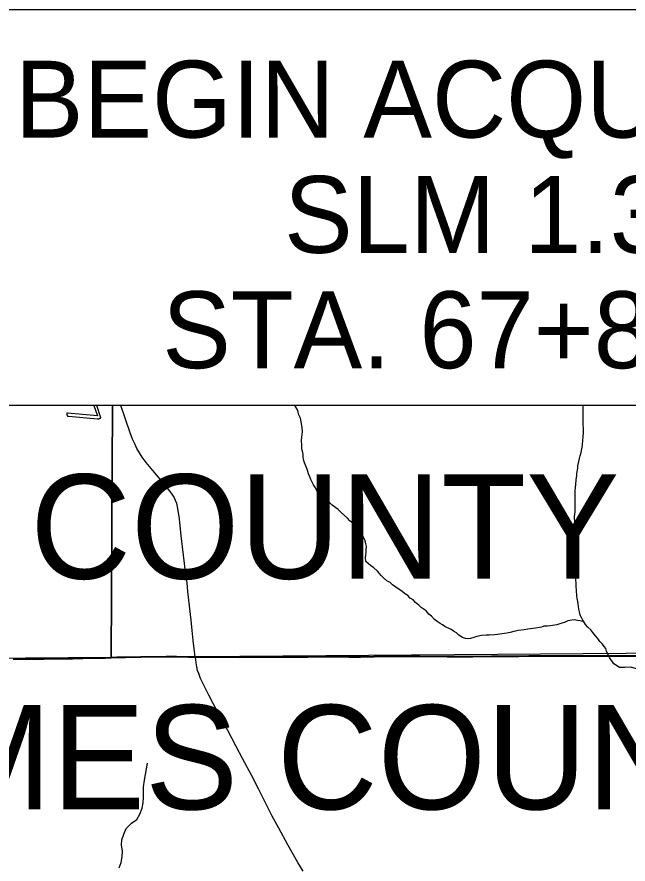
# Model space of a CAD drawing. Extents: x 0 to 34, y 0 to 22.
# Drawn here: x 4.059 to 5.172, y 15.823 to 17.365 of the extents above; entities that cross this region are included whole.
import ezdxf

# ---------------------------------------------------------------- set-up
doc = ezdxf.new("R2010")
doc.units = 0
for name, color, linetype in [('Default', 7, 'Continuous'), ('GM_X_County_Road', 7, 'Continuous'), ('GM_X_County_Road_Text', 7, 'Continuous'), ('GM_X_Minor_River', 7, 'Continuous'), ('GM_X_Section', 7, 'Continuous'), ('GM_X_Township_Road', 7, 'Continuous'), ('SH_Cut_Line', 7, 'Continuous')]:
    doc.layers.add(name, color=color, linetype=linetype)

msp = doc.modelspace()

# ---------------------------------------------------------------- linework, layer by layer
at = {"layer": 'Default'}
msp.add_lwpolyline([(3.9922, 17.3788), (5.9096, 17.3788), (5.9096, 16.6576), (3.9922, 16.6576)], close=True, dxfattribs=at)
for points in [[(4.0522, 16.1955), (4.0893, 16.196), (4.1079, 16.1964), (4.1358, 16.1969), (4.1606, 16.1968), (4.1792, 16.1971), (4.2195, 16.1983), (4.2412, 16.1991), (4.2567, 16.1994), (4.2846, 16.1997), (4.3311, 16.2004), (4.3498, 16.2004), (4.3715, 16.2), (4.3836, 16.2), (4.3963, 16.1999), (4.4243, 16.1997), (4.4646, 16.1994), (4.5174, 16.1997), (4.5887, 16.2), (4.6228, 16.2003), (4.6414, 16.2003), (4.663, 16.2), (4.6846, 16.2001), (4.7092, 16.2006), (4.7309, 16.201), (4.7433, 16.2011), (4.7587, 16.201), (4.7928, 16.2009), (4.8425, 16.2006), (4.8735, 16.2004), (4.889, 16.2007), (4.9231, 16.2011), (4.9448, 16.2013), (4.9727, 16.2014), (4.9914, 16.2016), (5.0069, 16.2018), (5.0348, 16.2017), (5.0689, 16.2016), (5.1, 16.2016), (5.1341, 16.2015), (5.1683, 16.2016), (5.2087, 16.2016)], [(5.2087, 16.2016), (5.1683, 16.2016), (5.1341, 16.2015), (5.1, 16.2016), (5.0689, 16.2016), (5.0348, 16.2017), (5.0069, 16.2018), (4.9914, 16.2016), (4.9727, 16.2014), (4.9448, 16.2013), (4.9231, 16.2011), (4.889, 16.2007), (4.8735, 16.2004), (4.8425, 16.2006), (4.7928, 16.2009), (4.7587, 16.201), (4.7433, 16.2011), (4.7309, 16.201), (4.7092, 16.2006), (4.6846, 16.2001), (4.663, 16.2), (4.6414, 16.2003), (4.6228, 16.2003), (4.5887, 16.2), (4.5174, 16.1997), (4.4646, 16.1994), (4.4243, 16.1997), (4.3963, 16.1999), (4.3836, 16.2), (4.3715, 16.2), (4.3498, 16.2004), (4.3311, 16.2004), (4.2846, 16.1997), (4.2567, 16.1994), (4.2412, 16.1991), (4.2195, 16.1983), (4.1792, 16.1971), (4.1606, 16.1968), (4.1358, 16.1969), (4.1079, 16.1964), (4.0893, 16.196), (4.0522, 16.1955)]]:
    msp.add_lwpolyline(points, dxfattribs=at)
at = {"layer": 'GM_X_County_Road'}
for points in [[(4.3838, 16.1994), (4.3832, 16.2047), (4.3802, 16.2294), (4.3781, 16.248), (4.3762, 16.2665), (4.3705, 16.3189), (4.3688, 16.3344), (4.3669, 16.3498), (4.3583, 16.4204), (4.3549, 16.4513), (4.3529, 16.4667), (4.3516, 16.4729), (4.35, 16.4789), (4.3479, 16.4849), (4.3452, 16.4906), (4.342, 16.496), (4.3384, 16.5011), (4.3267, 16.5157), (4.3065, 16.5395), (4.2947, 16.5538), (4.2871, 16.5636), (4.2821, 16.5714), (4.2776, 16.5795), (4.2735, 16.5878), (4.2698, 16.5963), (4.2654, 16.6079), (4.2564, 16.6344), (4.2483, 16.6576)], [(4.5801, 15.8093), (4.5707, 15.8254), (4.5523, 15.8578), (4.5358, 15.8878), (4.5241, 15.9098), (4.51, 15.9375), (4.4988, 15.9596), (4.4859, 15.9845), (4.47, 16.0148), (4.4585, 16.0368), (4.4422, 16.0668), (4.4245, 16.0996), (4.4087, 16.1299), (4.3973, 16.1521), (4.3934, 16.1606), (4.39, 16.1694), (4.3881, 16.1753), (4.3868, 16.1815), (4.3855, 16.1891), (4.3846, 16.1953), (4.3842, 16.1978), (4.3838, 16.1994)]]:
    msp.add_lwpolyline(points, dxfattribs=at)
at = {"layer": 'GM_X_County_Road_Text'}
msp.add_line((4.1528, 16.638), (4.2061, 16.6336), dxfattribs=at)
msp.add_lwpolyline([(4.2115, 16.6368), (4.2044, 16.6576), (4.1994, 16.6576), (4.2058, 16.6386), (4.1513, 16.6435)], dxfattribs=at)
for points in [[(4.1498, 16.6431), (4.1497, 16.6429), (4.1497, 16.6423)], [(4.1497, 16.6423), (4.1498, 16.6417), (4.1501, 16.6408)], [(4.1504, 16.6435), (4.15, 16.6434), (4.1498, 16.6431)], [(4.1501, 16.6408), (4.1504, 16.64), (4.1506, 16.6395)], [(4.1513, 16.6435), (4.1507, 16.6435), (4.1504, 16.6435)], [(4.1506, 16.6395), (4.1509, 16.639), (4.1511, 16.6386)], [(4.1511, 16.6386), (4.1514, 16.6383), (4.1518, 16.6382)], [(4.1518, 16.6382), (4.1522, 16.638), (4.1528, 16.638)], [(4.2061, 16.6336), (4.2066, 16.6336), (4.2071, 16.6336)], [(4.2071, 16.6336), (4.2076, 16.6336), (4.2081, 16.6337)], [(4.2081, 16.6337), (4.2085, 16.6337), (4.209, 16.6339)], [(4.209, 16.6339), (4.2094, 16.634), (4.2099, 16.6341)], [(4.2099, 16.6341), (4.2105, 16.6343), (4.2109, 16.6346)], [(4.2109, 16.6346), (4.2112, 16.6348), (4.2115, 16.6351)], [(4.2117, 16.6358), (4.2117, 16.6363), (4.2115, 16.6368)], [(4.2115, 16.6351), (4.2117, 16.6354), (4.2117, 16.6358)]]:
    msp.add_open_spline(points, degree=2, dxfattribs=at)
at = {"layer": 'GM_X_Minor_River'}
for points in [[(4.5775, 16.5946), (4.5778, 16.6), (4.5788, 16.6098), (4.5787, 16.6174), (4.5767, 16.628), (4.5755, 16.6348), (4.5724, 16.6409), (4.5709, 16.6454), (4.5701, 16.6496), (4.5662, 16.656), (4.5653, 16.6576)], [(5.1379, 16.1989), (5.1327, 16.21), (5.1312, 16.2149), (5.1281, 16.219), (5.1254, 16.2232), (5.1204, 16.2281), (5.1166, 16.2333), (5.1127, 16.2379), (5.1074, 16.2443), (5.1043, 16.2492), (5.0986, 16.254), (5.0943, 16.2589), (5.0897, 16.2665), (5.0878, 16.2706), (5.0847, 16.2759), (5.0835, 16.282), (5.0823, 16.2865), (5.0815, 16.2918), (5.0807, 16.2964), (5.0803, 16.3005), (5.0791, 16.3059), (5.0783, 16.3112), (5.0778, 16.321), (5.0773, 16.3278), (5.0773, 16.3328), (5.0768, 16.3411), (5.0767, 16.3529), (5.0763, 16.3608), (5.0762, 16.3662), (5.0757, 16.379), (5.0753, 16.3832), (5.0748, 16.3889), (5.0747, 16.4056), (5.0742, 16.4174), (5.074, 16.4329), (5.0747, 16.4435), (5.0745, 16.4553), (5.0756, 16.464), (5.0755, 16.4701), (5.0758, 16.48), (5.0754, 16.4868), (5.0753, 16.4963), (5.0756, 16.5016), (5.0763, 16.5088), (5.0766, 16.513), (5.0773, 16.5229), (5.0783, 16.5293), (5.0787, 16.5339), (5.0801, 16.5434), (5.0804, 16.5479), (5.0822, 16.5555), (5.0833, 16.5612), (5.0848, 16.5658), (5.0862, 16.5723), (5.0884, 16.5818), (5.0891, 16.5867), (5.0901, 16.6015), (5.0904, 16.608), (5.0904, 16.6148), (5.0899, 16.6243), (5.0902, 16.6288), (5.09, 16.6455), (5.0903, 16.6554), (5.0904, 16.6576)], [(5.0916, 16.2634), (5.0844, 16.2657), (5.0799, 16.266), (5.0738, 16.2671), (5.0696, 16.2667), (5.0621, 16.2655), (5.0575, 16.2632), (5.0477, 16.26), (5.0421, 16.2585), (5.0303, 16.2565), (5.025, 16.256), (5.0182, 16.2556), (5.0141, 16.254), (5.0035, 16.2524), (4.9993, 16.2516), (4.9895, 16.2504), (4.9827, 16.2492), (4.9724, 16.2476), (4.9641, 16.246), (4.9569, 16.2444), (4.9513, 16.2432), (4.9342, 16.2408), (4.9293, 16.24), (4.9195, 16.2395), (4.9134, 16.2395), (4.9051, 16.2387), (4.8964, 16.2367), (4.8911, 16.2351), (4.885, 16.2335), (4.8805, 16.2327), (4.8756, 16.2335), (4.8706, 16.2353), (4.8634, 16.2394), (4.8592, 16.2436), (4.8538, 16.2465), (4.8496, 16.2495), (4.8382, 16.2551), (4.834, 16.2585), (4.8298, 16.2607), (4.8245, 16.2645), (4.8195, 16.2679), (4.8138, 16.2739), (4.8092, 16.2776), (4.8042, 16.2837), (4.7954, 16.2897), (4.7908, 16.2938), (4.7847, 16.299), (4.7805, 16.3039), (4.7748, 16.3069), (4.7706, 16.3114), (4.7648, 16.3152), (4.7599, 16.3193), (4.7534, 16.3238), (4.7488, 16.3268), (4.7427, 16.3309), (4.7385, 16.3354), (4.7324, 16.3384), (4.7263, 16.344), (4.7221, 16.3478), (4.719, 16.3519), (4.7155, 16.3561), (4.7083, 16.3629), (4.7037, 16.3658), (4.6987, 16.3696), (4.6941, 16.3734), (4.6937, 16.3809), (4.6947, 16.3897), (4.6947, 16.3954), (4.6954, 16.4007), (4.6946, 16.4056), (4.693, 16.4109), (4.6907, 16.4166), (4.6884, 16.4211), (4.6841, 16.4275), (4.6807, 16.4324), (4.6753, 16.4377), (4.6715, 16.443), (4.6653, 16.4478), (4.6611, 16.4527), (4.6493, 16.4625), (4.6439, 16.4681), (4.6328, 16.476), (4.6286, 16.4805), (4.6244, 16.4846), (4.6198, 16.4884), (4.6168, 16.4933), (4.6095, 16.4974), (4.6049, 16.5023), (4.603, 16.5076), (4.5991, 16.5129), (4.5945, 16.5231), (4.5922, 16.5276), (4.5902, 16.5333), (4.5878, 16.542), (4.5828, 16.553), (4.5812, 16.5575), (4.5804, 16.5624), (4.58, 16.5689), (4.578, 16.5795), (4.5776, 16.5848), (4.5775, 16.5946)], [(5.3563, 16.0424), (5.3454, 16.052), (5.3356, 16.0612), (5.3254, 16.0711), (5.3157, 16.0784), (5.3025, 16.088), (5.29, 16.0919), (5.2791, 16.1003), (5.2682, 16.1084), (5.2577, 16.1168), (5.2475, 16.1275), (5.2377, 16.1341), (5.2284, 16.144), (5.2182, 16.1517), (5.2081, 16.1601), (5.1971, 16.1693), (5.1874, 16.1781), (5.1768, 16.1808), (5.1658, 16.1802), (5.156, 16.1803), (5.1462, 16.1872), (5.1379, 16.1989)], [(4.2451, 15.8154), (4.2486, 15.8252), (4.2505, 15.8355), (4.2514, 15.8464), (4.2496, 15.8567), (4.2504, 15.8665), (4.2535, 15.8771), (4.2581, 15.8873), (4.2677, 15.8971), (4.2776, 15.9034), (4.2826, 15.9132), (4.2872, 15.9242), (4.2888, 15.934), (4.2896, 15.9439), (4.2893, 15.9534), (4.2894, 15.9632), (4.2914, 15.9753), (4.2933, 15.9855), (4.2953, 15.9961), (4.2969, 16.006)]]:
    msp.add_lwpolyline(points, dxfattribs=at)
at = {"layer": 'GM_X_Section'}
for points in [[(3.9922, 17.1965), (3.585, 17.1952), (3.1987, 17.2046), (3.2147, 16.1912), (4.2304, 16.1993), (4.2331, 16.6576), (3.9922, 16.6576)], [(4.2331, 16.6576), (4.2304, 16.1993), (5.2468, 16.2071), (5.2442, 16.6576)]]:
    msp.add_lwpolyline(points, close=True, dxfattribs=at)
at = {"layer": 'GM_X_Township_Road'}
for points in [[(4.0524, 16.1949), (4.0895, 16.1955), (4.1081, 16.1958), (4.136, 16.1963), (4.1608, 16.1963), (4.1794, 16.1966), (4.2197, 16.1977), (4.2414, 16.1986), (4.2569, 16.1988), (4.2848, 16.1992), (4.3314, 16.1998), (4.35, 16.1998), (4.3717, 16.1995), (4.3838, 16.1994)], [(4.3838, 16.1994), (4.3965, 16.1993), (4.4245, 16.1992), (4.4648, 16.1988), (4.5176, 16.1991), (4.5889, 16.1995), (4.623, 16.1998), (4.6416, 16.1998), (4.6632, 16.1995), (4.6848, 16.1996), (4.7094, 16.2001), (4.7311, 16.2004), (4.7435, 16.2006), (4.759, 16.2005), (4.7931, 16.2003), (4.8427, 16.2), (4.8737, 16.1998), (4.8892, 16.2002), (4.9233, 16.2006), (4.945, 16.2008), (4.9729, 16.2008), (4.9916, 16.2011), (5.0071, 16.2013), (5.035, 16.2011), (5.0691, 16.201), (5.1002, 16.201), (5.1344, 16.201), (5.1685, 16.2011), (5.2089, 16.201)]]:
    msp.add_lwpolyline(points, dxfattribs=at)
at = {"layer": 'SH_Cut_Line'}
for points in [[(5.2087, 16.2016), (5.1683, 16.2016), (5.1341, 16.2015), (5.1, 16.2016), (5.0689, 16.2016), (5.0348, 16.2017), (5.0069, 16.2018), (4.9914, 16.2016), (4.9727, 16.2014), (4.9448, 16.2013), (4.9231, 16.2011), (4.889, 16.2007), (4.8735, 16.2004), (4.8425, 16.2006), (4.7928, 16.2009), (4.7587, 16.201), (4.7433, 16.2011), (4.7309, 16.201), (4.7092, 16.2006), (4.6846, 16.2001), (4.663, 16.2), (4.6414, 16.2003), (4.6228, 16.2003), (4.5887, 16.2), (4.5174, 16.1997), (4.4646, 16.1994), (4.4243, 16.1997), (4.3963, 16.1999), (4.3836, 16.2), (4.3715, 16.2), (4.3498, 16.2004), (4.3311, 16.2004), (4.2846, 16.1997), (4.2567, 16.1994), (4.2412, 16.1991), (4.2195, 16.1983), (4.1792, 16.1971), (4.1606, 16.1968), (4.1358, 16.1969), (4.1079, 16.1964), (4.0893, 16.196), (4.0522, 16.1955)], [(4.0522, 16.1955), (4.0893, 16.196), (4.1079, 16.1964), (4.1358, 16.1969), (4.1606, 16.1968), (4.1792, 16.1971), (4.2195, 16.1983), (4.2412, 16.1991), (4.2567, 16.1994), (4.2846, 16.1997), (4.3311, 16.2004), (4.3498, 16.2004), (4.3715, 16.2), (4.3836, 16.2), (4.3963, 16.1999), (4.4243, 16.1997), (4.4646, 16.1994), (4.5174, 16.1997), (4.5887, 16.2), (4.6228, 16.2003), (4.6414, 16.2003), (4.663, 16.2), (4.6846, 16.2001), (4.7092, 16.2006), (4.7309, 16.201), (4.7433, 16.2011), (4.7587, 16.201), (4.7928, 16.2009), (4.8425, 16.2006), (4.8735, 16.2004), (4.889, 16.2007), (4.9231, 16.2011), (4.9448, 16.2013), (4.9727, 16.2014), (4.9914, 16.2016), (5.0069, 16.2018), (5.0348, 16.2017), (5.0689, 16.2016), (5.1, 16.2016), (5.1341, 16.2015), (5.1683, 16.2016), (5.2087, 16.2016)]]:
    msp.add_lwpolyline(points, dxfattribs=at)

# ---------------------------------------------------------------- texts
at = {"layer": 'Default'}
for s, height, p in [('BEGIN ACQUISITION', 0.14, (4.0553, 17.1456)), ('SLM 1.32', 0.14, (4.5455, 16.9356)), ('STA. 67+85.00', 0.14, (4.3237, 16.7256)), ('WAYNE COUNTY', 0.19, (3.081, 16.3422)), ('HOLMES COUNTY', 0.19, (3.3888, 15.9222))]:
    msp.add_text(s, height=height, dxfattribs=at).set_placement(p)

doc.saveas('drawing.dxf')
